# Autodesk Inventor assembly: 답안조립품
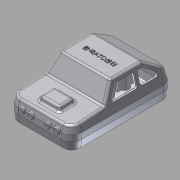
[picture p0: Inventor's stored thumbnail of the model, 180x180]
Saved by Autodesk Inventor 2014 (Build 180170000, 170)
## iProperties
Created: 2015-05
Part Number: 답안조립품
Document SubType Name: Assembly
Designer: Administrator
Author: Administrator
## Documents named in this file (7)
- C:\Documents and Settings\Administrator\바탕 화면\450508V1013\답안조립품.iam
- C:\Documents and Settings\Administrator\바탕 화면\450508V1013\본체.ipt
- C:\Documents and Settings\Administrator\바탕 화면\450508V1013\커버.ipt
- C:\Documents and Settings\Administrator\바탕 화면\450508V1013\M4x10.ipt
- C:\Documents and Settings\Administrator\바탕 화면\450508V1013\바퀴.ipt
- C:\Documents and Settings\Administrator\바탕 화면\450508V1013\바퀴고정부.ipt
- C:\Documents and Settings\Administrator\바탕 화면\450508V1013\M2x4.ipt
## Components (20 placed, 2 different names)
1. M4x10:1
2. M4x10:2
3. M4x10:3
4. M4x10:4
5. M2x4:1
6. M2x4:2
7. M2x4:3
8. M2x4:4
9. M2x4:5
10. M2x4:6
11. M2x4:9
12. M2x4:10
13. M2x4:11
14. M2x4:12
15. M2x4:13
16. M2x4:14
17. M2x4:15
18. M2x4:16
19. M2x4:17
20. M2x4:18
